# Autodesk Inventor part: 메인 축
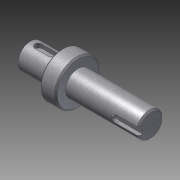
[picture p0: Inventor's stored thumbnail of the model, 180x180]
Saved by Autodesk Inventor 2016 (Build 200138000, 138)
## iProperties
Created: 2014-10
Part Number: 메인 축
Document SubType Name: Modeling
Designer: KYOUNG IL JANG
Density: 7.86 g/cm^3
Mass: 230.24 g
Surface Area: 74.3518 cm^2
Volume: 29.2926 cm^3
Material: 강철, 연강
Appearance: 금속-강(스테인리스, 브러시됨)
Author: SeoGD™ [www.esajin.kr]
Revision Number: 1
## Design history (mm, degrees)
sketch "스케치1"
  geometry: L1 (10.497, -57.5)-(92.497, -57.5); L2 (10.497, -66)-(32.497, -66); L3 (32.497, -72.5)-(46.5, -72.5); L4 (46.5, -66)-(92.497, -66); L5 (92.497, -66)-(92.497, -57.5); L6 (10.497, -66)-(10.497, -57.5); L7 (46.5, -69.749)-(46.5, -45.251) reference; L8 (46.5, -72.5)-(46.5, -66); L9 (32.497, -72.5)-(32.497, -66); L10 (32.497, -35)-(32.497, -80) reference; 2 further points
  constraints: 16 end point, 2 parallel, 2 perpendicular, 2 point on line, 1 collinear, 1 horizontal, 1 midpoint
  dimensions: "d0" = 17 diameter of L4 L1; "d1" = 30 diameter of L3 L1; "d2" = 22 distance of L2.start L2.end; "d5" = 17 diameter of L2 L1; "d19" = 60 distance between parallel lines of L5 L9
revolve "회전1" sketch "스케치1" stored, may be unused: angle "d4" = 90 deg
feature "면 이동2"
chamfer "모따기1" distance "d6" = 1; stored, may be unused: second distance "d7" = 2, angle "d8" = 45 deg
node "작업 평면1"
sketch "스케치2"
  geometry: L1 (-11, -7.5)-(-11, 7.5) reference; L2 (-4.5, 2.5)-(4.5, 2.5); L3 (4.5, -2.5)-(-4.5, -2.5); A1 r 2.5 centre (4.5, 0) between (4.5, -2.5) and (4.5, 2.5); A2 r 2.5 centre (-4.5, 0) between (-4.5, 2.5) and (-4.5, -2.5); 2 further points
  constraints: 4 end point, 4 point on circle, 4 tangent, 2 centre point, 1 horizontal alignment, 1 midpoint, 1 parallel, 1 perpendicular
  dimensions: "d9" = 5 distance between parallel lines of L3 L2; "d10" = 14 dimension on A1 A2; "d11" = 4 distance edge to line of A2 L1
extrude "돌출1" cut sketch "스케치2" distance "d12" = 3; taper "d13" = 0 deg
node "작업 평면2"
sketch "스케치3"
  geometry: L1 (22.998, 7.5)-(22.998, -7.5) reference; L2 (22.998, 2.5)-(7.498, 2.5); L3 (7.498, -2.5)-(22.998, -2.5); A1 r 2.5 centre (7.498, 0) between (7.498, 2.5) and (7.498, -2.5); 2 further points
  constraints: 4 end point, 2 perpendicular, 2 point on circle, 2 point on line, 2 tangent, 1 centre point, 1 horizontal alignment, 1 midpoint
  dimensions: "d14" = 5 distance between parallel lines of L3 L2; "d15" = 18 dimension on A1 L1
extrude "돌출2" cut sketch "스케치3" distance "d16" = 3; taper "d17" = 0 deg
node "솔리드1"
node "참조4"
node "참조5"
